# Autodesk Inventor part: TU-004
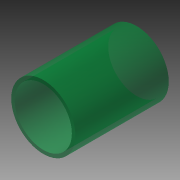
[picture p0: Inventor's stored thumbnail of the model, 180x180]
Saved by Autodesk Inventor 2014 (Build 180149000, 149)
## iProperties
Shininess: 64.0
Angle Display Precision: 2
Document Length Units: 11269
Document Angle Units: 11279
Document Time Units: 11290
Document Mass Units: 11286
Document Length Units Precision: 3
Document Angle Units Precision: 2
Created: 2002-07
Part Number: TU-004
Document SubType Name: Modeling
Designer: PN
Description: Cylinder Tube
Density: 8.08 g/cm^3
Mass: 184.955 g
Surface Area: 189.956 cm^2
Volume: 22.8904 cm^3
Material: Stainless Steel
Appearance: Green (Clear)
Density: 0.0
Volumn: 0.0
Area: 0.0
PropertySet Name: Model Information
Control State: 0
Master: False
Checked Out: False
LENGTH: 1.000 in
Author: PN
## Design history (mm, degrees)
sketch "Sketch1"
  geometry: C1 r 23 at (0, 0); C2 r 20.5 at (0, 0); 1 further point
  constraints: 2 centre point, 2 coincident
  dimensions: "d0" = 46 diameter of C1; "d1" = 41 diameter of C2
extrude "Extrusion1" new body sketch "Sketch1" stored distance "d2" = 67; taper "d3" = 0 deg
body "Solid1"
other parameters: "LENGTH" = 25.4 [user parameter]
